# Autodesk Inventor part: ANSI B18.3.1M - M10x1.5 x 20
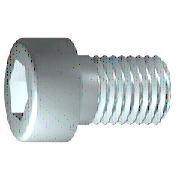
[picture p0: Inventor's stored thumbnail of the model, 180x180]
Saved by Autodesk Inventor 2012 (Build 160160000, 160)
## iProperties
Created: 2011-02
Part Number: ANSI B18.3.1M - M10x1.5 x 20
Material: Steel, Mild
Description: Broached Socket Head Cap Screw - Metric
Document SubType Name: Modeling
Standard: ANSI B18.3.1M
Designer: jrr70267
Standard Revision: 1979
Standards Organization: ANSI
Language: en-US
Size Designation: M10x1.5 x 20
Categories: <MemberInstance><Categories><Category DisplayName="Fasteners" InternalName="e4da775c-781d-43d5-af7c-5136215cf5a6" Mnemonic="FSTN"><Category DisplayName="Bolts"
Density: 1 g/cm^3
IsCustomPart: 0
Author: jrr70267
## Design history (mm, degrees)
body "Solid1"
workplane "Work Plane1"
revolve "Body" stored, may be unused: angle "d10" = 90 deg
sketch "Sketch2"
  geometry: L1 (0, -11.2)-(0, 11.2) reference; L2 (-11.2, 0)-(11.2, 0) reference; L3 (4.619, 0)-(2.309, -4); L4 (2.309, -4)-(-2.309, -4); L5 (-2.309, -4)-(-4.619, 0); L6 (-4.619, 0)-(-2.309, 4); L7 (-2.309, 4)-(2.309, 4); L8 (2.309, 4)-(4.619, 0); 2 further points
  constraints: 12 end point, 1 coincident, 1 horizontal alignment, 1 point on line, 12 other
extrude "Slot" join sketch "Sketch2" taper "d9" = 0 deg; stored distance "d11" = 10
fillet "Fillet2" dims "d16" = 1 (= RR)
feature "Thread" dims "d12" = 17.15965 (= GEL), "d13" = 0
chamfer "Chamfer1" distance "d14" = 0.92018 (= -0.5 x SPD + 0.5 x GD); stored, may be unused: second distance "d15" = 0.92018 (= GUL), angle "d27" = 45 deg
fillet "Fillet1" dims "d29" = 0.4 (= R)
sketch "Sketch1"
  geometry: L1 (-2.333, 0)-(20, 0); L2 (20, 0)-(20, 5); L3 (20, 5)-(2.84, 5); L4 (2.84, 5)-(1.92, 5); L5 (1.92, 5)-(0, 5); L6 (0, 5)-(0, 8); L7 (0, 8)-(-10, 8); L8 (-10, 8)-(-10, 4.619); L9 (-10, 4.619)-(-5, 4.619); L10 (-5, 4.619)-(-2.333, 0); L11 (-16, 0)-(26, 0) reference; L12 (0, -1.6)-(0, 9.6) reference; L13 (2.84, 5)-(0, 5)
  constraints: 22 end point, 6 parallel, 3 collinear, 1 horizontal, 1 perpendicular, 1 point on line
  dimensions: "d0" = 17.15965 distance from line of L3.end L2 (= GEL); "d1" = 0.92018 distance of L4.end L3.end (= GAL); "d2" = 10 distance between parallel lines of L8 L6 (= KOH); "d3" = 5 distance of L8.end L9.end (= INTI); "d4" = 60 deg angle of L10 L1; "d5" = 10 diameter of L3 L1 (= GD); "d6" = 10 diameter of L5 L1 (= BDM); "d7" = 9.2376 diameter of L9 L1 (= 1.1547 x SW); "d8" = 16 diameter of L7 L1 (= KOD); "d19" = 20 distance between parallel lines of L2 L6 (= NLG)
other parameters: "GD" = 10 (= NND) [user parameter; used in 2 equation terms], "NLG" = 20 [user parameter; used in 1 equation term], "GEL" = 17.15965 [user parameter; used in 2 equation terms], "KOD" = 16 [user parameter; used in 2 equation terms], "KOH" = 10 [user parameter; used in 1 equation term], "INTI" = 5 [user parameter; used in 1 equation term], "GAL" = 0.92018 (= 0.61345 x PTC) [user parameter; used in 1 equation term], "GUL" = 0.92018 (= 0.61345 x PTC) [user parameter; used in 1 equation term], "BDM" = 10 (= NND) [user parameter; used in 1 equation term], "SW" = 8 [user parameter; used in 2 equation terms], "RR" = 1 [user parameter; used in 1 equation term], "SPD" = 8.15965 [user parameter; used in 1 equation term], "d17" = 0, "d18" = 0, "d28" = 0.4 (= R), "R" = 0.4 [user parameter; used in 2 equation terms], "TOA" = 30 deg [user parameter], "KOD1" = 16 (= KOD) [user parameter], "TPU" = 6.66667 (computed from PTC) [user parameter], "PTC" = 1.5 [user parameter; used in 4 equation terms], "E0" = 9.24 (= 1.155 x SW) [user parameter], "GD1" = 8.15965 (= THREADDIA - 1.2269 x PTC) [user parameter]
